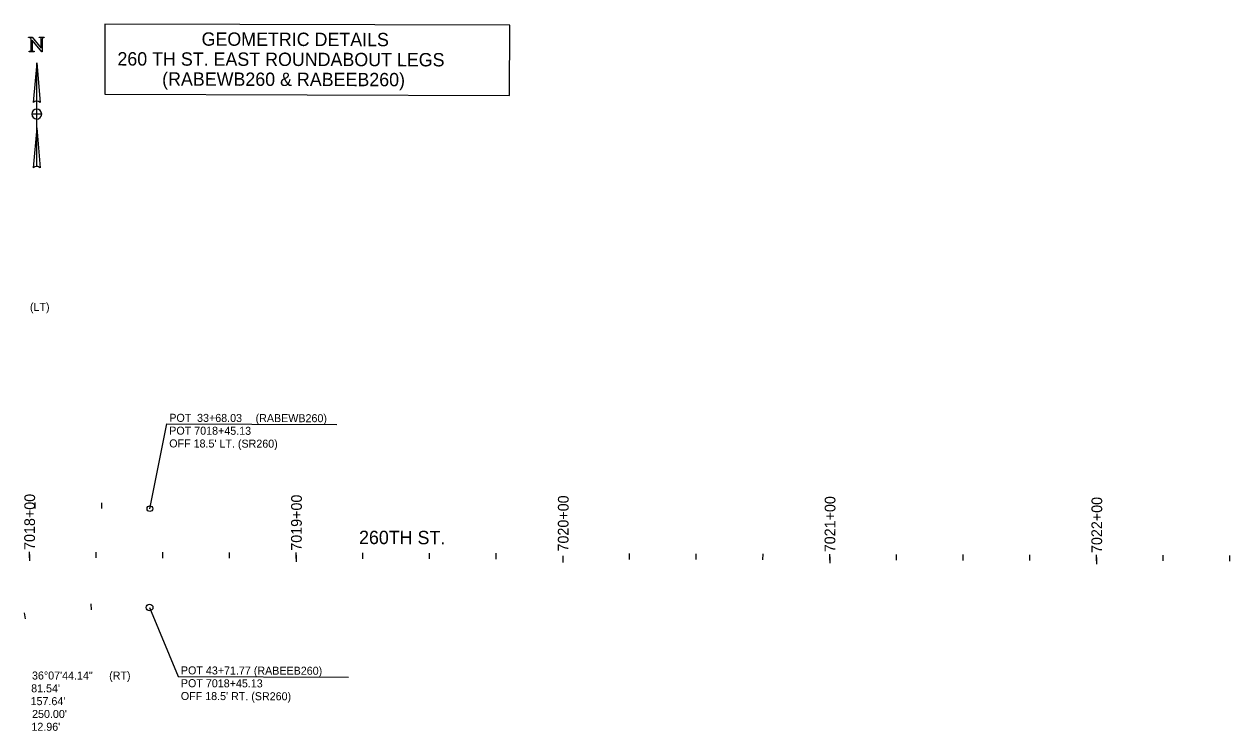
# Model space of a CAD drawing. Extents: x 5195296 to 5198948, y 3709168 to 3709552.
# Drawn here: x 5197595.9 to 5198047.8, y 3709284.4 to 3709549.2 of the extents above; entities that cross this region are included whole.
import ezdxf

# ---------------------------------------------------------------- set-up
doc = ezdxf.new("R2010")
doc.units = 0
for name, color, linetype in [('dsnAlignmentStation', 7, 'Continuous'), ('dsnGeopakCellProfile', 7, 'Continuous'), ('dsnProfileEntranceGradeProp', 7, 'Continuous')]:
    doc.layers.add(name, color=color, linetype=linetype)

msp = doc.modelspace()

# ---------------------------------------------------------------- linework, layer by layer
at = {"layer": 'dsnAlignmentStation'}
for p, q in [((5197597.84, 3709350.5), (5197597.83, 3709348.05)), ((5197622.83, 3709349.21), (5197622.84, 3709351.39)), ((5197647.83, 3709349.13), (5197647.84, 3709351.32)), ((5197672.83, 3709349.06), (5197672.84, 3709351.24)), ((5197697.84, 3709350.21), (5197697.83, 3709347.76)), ((5197722.83, 3709348.92), (5197722.84, 3709351.1)), ((5197747.83, 3709348.84), (5197747.84, 3709351.03)), ((5197772.83, 3709348.77), (5197772.84, 3709350.96)), ((5197797.84, 3709349.92), (5197797.83, 3709347.48)), ((5197822.83, 3709348.63), (5197822.84, 3709350.81)), ((5197847.83, 3709348.55), (5197847.84, 3709350.74)), ((5197872.83, 3709348.48), (5197872.84, 3709350.67)), ((5197897.84, 3709349.63), (5197897.83, 3709347.19)), ((5197922.83, 3709348.34), (5197922.84, 3709350.52)), ((5197947.83, 3709348.27), (5197947.84, 3709350.45)), ((5197972.83, 3709348.19), (5197972.84, 3709350.38)), ((5197997.84, 3709349.35), (5197997.83, 3709346.9)), ((5198022.83, 3709348.05), (5198022.84, 3709350.23)), ((5198047.83, 3709347.98), (5198047.84, 3709350.16))]:
    msp.add_line(p, q, dxfattribs=at)
at = {"layer": 'dsnGeopakCellProfile'}
for p, q in [((5197600.59, 3709534.75), (5197599.29, 3709519.81)), ((5197600.59, 3709534.75), (5197601.9, 3709519.81)), ((5197600.59, 3709520.37), (5197600.59, 3709534.75)), ((5197600.59, 3709495.91), (5197600.59, 3709534.75)), ((5197600.59, 3709520.34), (5197600.59, 3709520.37)), ((5197600.59, 3709515.5), (5197600.59, 3709517.38)), ((5197600.59, 3709515.5), (5197598.72, 3709515.5)), ((5197602.47, 3709515.5), (5197598.72, 3709515.5)), ((5197602.47, 3709515.5), (5197600.59, 3709515.5)), ((5197600.59, 3709513.63), (5197600.59, 3709515.5)), ((5197600.59, 3709510.32), (5197599.29, 3709495.38)), ((5197600.59, 3709495.91), (5197600.59, 3709510.32)), ((5197600.59, 3709510.32), (5197601.9, 3709495.38)), ((5197599.98, 3709367.77), (5197599.99, 3709369.96)), ((5197624.98, 3709367.7), (5197624.99, 3709369.88)), ((5197621.16, 3709329.76), (5197620.98, 3709331.94)), ((5197596.4, 3709326.42), (5197596, 3709328.57))]:
    msp.add_line(p, q, dxfattribs=at)
msp.add_lwpolyline([(5197777.91, 3709548.76), (5197626.18, 3709549.2), (5197626.11, 3709522.94), (5197777.84, 3709522.51)], close=True, dxfattribs=at)
msp.add_lwpolyline([(5197777.91, 3709548.76), (5197626.18, 3709549.2), (5197626.11, 3709522.94), (5197777.84, 3709522.51)], close=True, dxfattribs=at)
for points in [[(5197597.46, 3709544.36), (5197598.94, 3709544.36), (5197602.31, 3709540.24), (5197602.31, 3709543.41)], [(5197597.46, 3709544.22), (5197597.46, 3709544.36)], [(5197598.54, 3709539.82), (5197598.54, 3709543.64)], [(5197602.67, 3709543.41), (5197602.67, 3709538.78), (5197602.52, 3709538.78), (5197598.9, 3709543.21), (5197598.9, 3709539.82)], [(5197601.72, 3709544.22), (5197601.53, 3709544.22), (5197601.53, 3709544.36), (5197603.44, 3709544.36), (5197603.44, 3709544.22), (5197603.25, 3709544.22)], [(5197599.48, 3709539.01), (5197599.67, 3709539.01), (5197599.67, 3709538.87), (5197597.76, 3709538.87), (5197597.76, 3709539.01), (5197597.96, 3709539.01)], [(5197643.01, 3709367.65), (5197649.32, 3709399.38), (5197713.06, 3709399.2)], [(5197642.91, 3709330.65), (5197653.67, 3709304.75), (5197717.41, 3709304.57)]]:
    msp.add_lwpolyline(points, dxfattribs=at)
for centre, radius in [((5197643.01, 3709367.65), 1.07), ((5197642.91, 3709330.65), 1.25)]:
    msp.add_circle(centre, radius, dxfattribs=at)
for centre, start, end in [((5197600.59, 3709515.5), 90, 89.4464), ((5197600.59, 3709518.46), 45.7867, 134.2133), ((5197600.59, 3709518.46), 90, 134.2134), ((5197600.59, 3709515.5), 360, 89.9989), ((5197600.59, 3709515.5), 180, 270), ((5197600.59, 3709494.04), 45.7867, 134.2134), ((5197600.59, 3709494.04), 45.7867, 90)]:
    msp.add_arc(centre, 1.87, start, end, dxfattribs=at)
for points in [[(5197598.54, 3709543.64), (5197598.3, 3709543.92), (5197598.18, 3709544.01), (5197598.06, 3709544.1), (5197597.82, 3709544.18), (5197597.7, 3709544.22), (5197597.46, 3709544.22)], [(5197602.31, 3709543.41), (5197602.31, 3709543.92), (5197602.2, 3709544.05), (5197602.05, 3709544.22), (5197601.72, 3709544.22)], [(5197603.25, 3709544.22), (5197602.9, 3709544.22), (5197602.76, 3709544.01), (5197602.67, 3709543.88), (5197602.67, 3709543.41)], [(5197597.96, 3709539.01), (5197598.31, 3709539.01), (5197598.45, 3709539.23), (5197598.54, 3709539.36), (5197598.54, 3709539.82)], [(5197598.9, 3709539.82), (5197598.9, 3709539.31), (5197599.01, 3709539.18), (5197599.16, 3709539.01), (5197599.48, 3709539.01)]]:
    msp.add_open_spline(points, degree=3, dxfattribs=at)
at = {"layer": 'dsnProfileEntranceGradeProp'}
for p, q in [((5197597.83, 3709349.28), (5197597.84, 3709351.46)), ((5197697.83, 3709348.99), (5197697.84, 3709351.17)), ((5197797.84, 3709349.92), (5197797.83, 3709347.48)), ((5197897.83, 3709348.41), (5197897.84, 3709350.59)), ((5197997.83, 3709348.12), (5197997.84, 3709350.31))]:
    msp.add_line(p, q, dxfattribs=at)

# ---------------------------------------------------------------- texts
at = {"layer": 'dsnAlignmentStation'}
for s, p in [('7018+00', (5197599.92, 3709352.18)), ('7019+00', (5197699.92, 3709351.89)), ('7020+00', (5197799.92, 3709351.6)), ('7021+00', (5197899.92, 3709351.32)), ('7022+00', (5197999.92, 3709351.03))]:
    msp.add_text(s, height=4.008, rotation=89.8345, dxfattribs=at).set_placement(p)
at = {"layer": 'dsnGeopakCellProfile'}
for s, height, p in [('GEOMETRIC DETAILS', 5, (5197662.38, 3709541.11)), ('260 TH ST. EAST ROUNDABOUT LEGS', 5, (5197630.83, 3709533.7)), ('(RABEWB260 & RABEEB260)', 5, (5197647.59, 3709526.16)), ('POT ', 3, (5197650.29, 3709400.2)), ('33+68.03', 3, (5197660.7, 3709400.17)), (' (RABEWB260)', 3, (5197681.51, 3709400.11)), ('POT 7018+45.13', 3, (5197650.27, 3709395.4)), ("OFF 18.5' LT. (SR260)", 3, (5197650.26, 3709390.6)), ('260TH ST.', 5, (5197721.4, 3709354.4)), ('POT 43+71.77 (RABEEB260)', 3, (5197654.64, 3709305.57)), ('POT 7018+45.13', 3, (5197654.63, 3709300.77)), ("OFF 18.5' RT. (SR260)", 3, (5197654.61, 3709295.97))]:
    msp.add_text(s, height=height, rotation=359.8345, dxfattribs=at).set_placement(p)
for s, p in [(' (LT)', (5197596.94, 3709441.74)), ('36°07\'44.14"', (5197598.82, 3709303.64)), (' (RT)', (5197626.62, 3709303.64)), ("81.54'", (5197598.51, 3709298.84)), ("157.64'", (5197598.29, 3709294.04)), ("250.00'", (5197598.86, 3709289.24)), ("12.96'", (5197598.6, 3709284.44))]:
    msp.add_text(s, height=3, dxfattribs=at).set_placement(p)
at = {"layer": 'dsnProfileEntranceGradeProp'}
msp.add_text('7020+00', height=4.008, rotation=89.8345, dxfattribs=at).set_placement((5197799.92, 3709351.6))

doc.saveas('drawing.dxf')
